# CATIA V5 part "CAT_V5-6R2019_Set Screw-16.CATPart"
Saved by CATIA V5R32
Part number: Set Screw-16
Bounding box of the stored display mesh (mm): x -5.916 to 5.916, y -5.998 to 5.998, z -1.5 to 20.171
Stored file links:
  D:\PROJECTS\Project 2022\CATIA V5 6R 2022\Resources\Tutorial Files\c16_catia_v5_6r2022_tut\Bench vice\CAT_V5-6R2019_Set Screw-16.CATPart
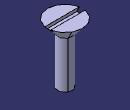
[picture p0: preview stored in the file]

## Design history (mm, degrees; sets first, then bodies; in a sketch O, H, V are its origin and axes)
Body1 (main body)
  Sketch1 on yz-plane, origin (0, 0, 0), H (0, 1, 0), V (0, 0, 1)
    point P1 (0, -1.5)
    line L1 (0, -1.5) -> (2.5, 0)
    point P2 (2.5, 0)
    line L2 (2.5, 0) -> (2.5, 16)
    line L3 (2.5, 16) -> (6, 20.1711)
    point P4 (6, 20.1711)
    line L4 (6, 20.1711) -> (0, 20.1711)
    point P5 (0, 20.1711)
    line L5 (0, 20.1711) -> (0, -1.5)
    length L2 = 16
    distance L2 L5 = 2.5
    distance H P1 = 1.5
    distance P4 L5 = 6
    angle L3 L5 = 40
    coincidence: P1 V, P2 H, P5 V
    vertical: L2 V, L5 V
    horizontal: L4 H
  Shaft1: profile Sketch1, axis edge of Sketch1, angle 360
  Sketch2 on yz-plane, origin (0, 0, 0), H (0, 1, 0), V (0, 0, 1)
    line L1 (-1, 20.1711) -> (1, 20.1711)
    line L2 (1, 20.1711) -> (1, 19.1711)
    line L3 (1, 19.1711) -> (-1, 19.1711)
    line L4 (-1, 19.1711) -> (-1, 20.1711)
    reference projected line E1 (-6, 20.1711) -> (6, 20.1711) from edge of Shaft1
    distance V L2 = 1
    length L1 = 2
    length L2 = 1
    horizontal: L1 H, L3 H
    vertical: L2 V, L4 V
    coincidence: L1 E1
  Pocket1: profile Sketch2, direction (-1, 0, 0), length 16, mirrored extent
